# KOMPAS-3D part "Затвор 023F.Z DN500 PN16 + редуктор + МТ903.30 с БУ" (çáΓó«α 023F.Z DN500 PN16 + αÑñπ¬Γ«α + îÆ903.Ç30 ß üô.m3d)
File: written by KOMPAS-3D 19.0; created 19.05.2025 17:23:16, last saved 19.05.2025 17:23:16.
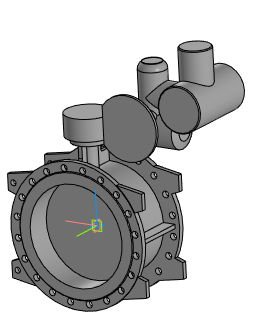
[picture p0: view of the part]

Document properties: Полное имя файла: Затвор 023F.Z DN500 PN16 + редуктор + МТ903.30 с БУ.a3d

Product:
- Part/product: Затвор 023F.Z DN500 PN16 + редуктор + МТ903.30 с БУ
    Масса: 607.244

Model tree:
1. Операция без истории:1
